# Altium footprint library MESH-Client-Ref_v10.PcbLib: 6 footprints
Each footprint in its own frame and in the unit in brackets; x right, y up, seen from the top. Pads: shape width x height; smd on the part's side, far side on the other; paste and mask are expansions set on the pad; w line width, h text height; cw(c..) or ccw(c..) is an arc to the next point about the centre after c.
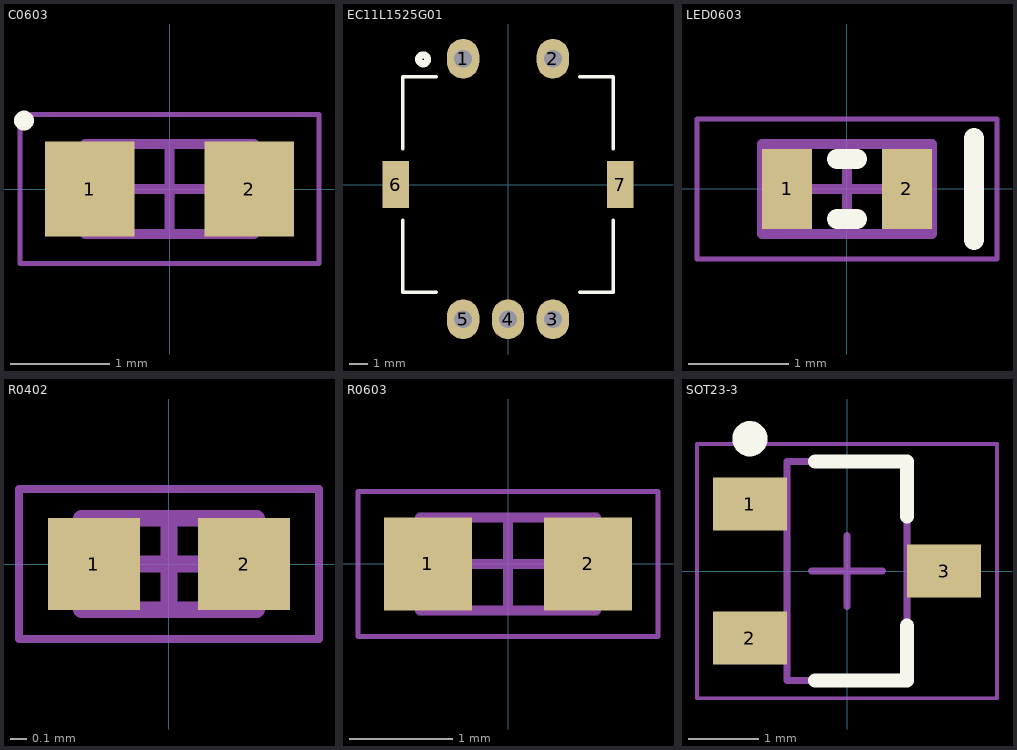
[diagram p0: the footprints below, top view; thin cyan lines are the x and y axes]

## C0603 [mm] "Chip Capacitor, 2-Leads, Body 1.60x0.80mm, IPC Medium Density"
height 0.6
pads (2):
  rect 0.9x0.95 smd: 1(-0.8,0) 2(0.8,0)
Top Overlay:
  circle w0.1: c-1.462,0.687 r0.05
Mechanical 13:
  lines w0.1: -0.85,-0.45 -0.85,0.45 0.85,0.45 0.85,-0.45 -0.85,-0.45
Mechanical 15:
  lines w0.05: -1.5,-0.75 -1.5,0.75 1.5,0.75 1.5,-0.75 -1.5,-0.75
  lines w0.1: -0.45,0 0.45,0 ; 0,-0.45 0,0.45
3D body "C0603.step": height 0.6, standoff 0, extent -0.85,-0.45 0.85,0.45

## EC11L1525G01 [mm]
pads (7):
  oval 1.8x2.2 hole 1: 1(-2.5,7) 2(2.5,7) 3(2.5,-7.5) 4(0,-7.5) 5(-2.5,-7.5)
  rect 1.5x2.6 smd: 6(-6.25,0) 7(6.25,0)
Top Overlay:
  circle w0.4: c-4.725,6.967 r0.25
  lines w0.2: -5.85,-2 -5.85,-6 -4,-6 ; -5.85,2 -5.85,6 -4,6 ; 4,-6 5.85,-6 5.85,-2 ; 4,6 5.85,6 5.85,2

## LED0603 [mm] "Chip Diode, 2-Leads, Body 1.65x0.85mm, IPC Medium Density"
height 0.6
pads (2):
  rect 0.5x0.8 smd: 1(-0.6,0) 2(0.6,0)
Top Overlay:
  lines w0.2: -0.1,-0.3 0.1,-0.3 ; -0.1,0.3 0.1,0.3 ; 1.27,-0.508 1.27,0.508
Mechanical 13:
  lines w0.1: -0.85,-0.45 0.85,-0.45 0.85,0.45 -0.85,0.45 -0.85,-0.45
Mechanical 15:
  lines w0.05: -1.5,-0.7 1.5,-0.7 1.5,0.7 -1.5,0.7 -1.5,-0.7
  lines w0.1: -0.45,0 0.45,0 ; 0,-0.45 0,0.45
3D body "LED0603.step": height 0.6, standoff 0, extent -0.85,-0.45 0.85,0.45

## R0402 [mm] "Chip Resistor, 2-Leads, Body 1.00x0.50mm, IPC Medium Density"
height 0.4
pads (2):
  rect 0.55x0.55 smd: 1(-0.45,0) 2(0.45,0)
Mechanical 13:
  lines w0.1: -0.525,-0.275 0.525,-0.275 0.525,0.275 -0.525,0.275 -0.525,-0.275
Mechanical 15:
  lines w0.05: -0.9,-0.45 0.9,-0.45 0.9,0.45 -0.9,0.45 -0.9,-0.45
  lines w0.1: -0.275,0 0.275,0 ; 0,-0.275 0,0.275
3D body: height 0.4, standoff 0, extent 0.325,-0.275 0.525,0.275
3D body: height 0.4, standoff 0, extent -0.525,-0.275 -0.325,0.275
3D body: height 0.4, standoff 0, extent -0.325,-0.275 0.325,0.275

## R0603 [mm] "Chip Resistor, 2-Leads, Body 1.60x0.80mm, IPC Medium Density"
height 0.55
pads (2):
  rect 0.85x0.9 smd: 1(-0.775,0) 2(0.775,0)
Mechanical 13:
  lines w0.1: -0.85,-0.45 -0.85,0.45 0.85,0.45 0.85,-0.45 -0.85,-0.45
Mechanical 15:
  lines w0.05: -1.45,-0.7 -1.45,0.7 1.45,0.7 1.45,-0.7 -1.45,-0.7
  lines w0.1: -0.45,0 0.45,0 ; 0,-0.45 0,0.45
3D body "R0603.step": height 0.6, standoff 0, extent -0.85,-0.45 0.85,0.45

## SOT23-3 [mm] "SOT23, 3-Leads, Body 2.96x2.83mm, Pitch 0.95mm, IPC Medium Density"
height 1.5
pads (3):
  rect 1.05x0.75 smd: 1(-1.375,0.95) 2(-1.375,-0.95) 3(1.375,0)
Top Overlay:
  circle w0.25: c-1.375,1.875 r0.125
  lines w0.2: -0.45,-1.55 0.85,-1.55 0.85,-0.775 ; -0.45,1.55 0.85,1.55 0.85,0.775
Mechanical 13:
  lines w0.1: -0.85,-1.55 0.85,-1.55 0.85,1.55 -0.85,1.55 -0.85,-1.55
Mechanical 15:
  lines w0.05: -2.125,-1.8 2.125,-1.8 2.125,1.8 -2.125,1.8 -2.125,-1.8
  lines w0.1: -0.5,0 0.5,0 ; 0,-0.5 0,0.5
3D body "SOT23-3.step": height 1.5, standoff 0, extent -1.5,-1.55 1.5,1.55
